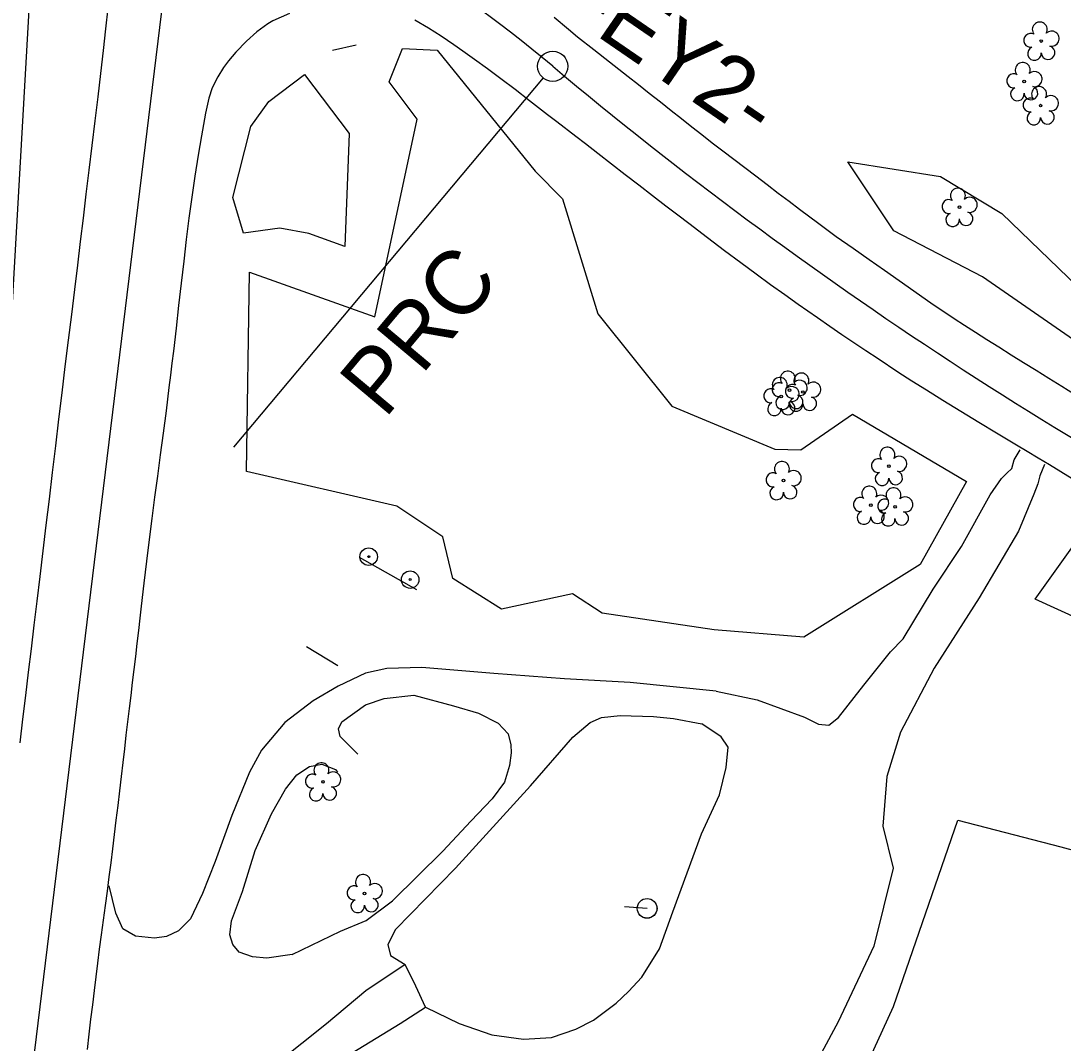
# Model space of a CAD drawing. Extents: x 479429 to 482809, y 488118 to 492379.
# Drawn here: x 481361.5 to 481621, y 490888.5 to 491143.2 of the extents above; entities that cross this region are included whole.
import ezdxf

# ---------------------------------------------------------------- set-up
doc = ezdxf.new("R2010")
doc.units = 0
for name, color, linetype in [('Exist Horizontal Alignment', 7, 'Continuous'), ('Exist Horizontal Alignment Direction Label', 7, 'Continuous'), ('Exist Other Culture Sign', 7, 'Continuous'), ('Exist Other Culture Sign Post CELL', 7, 'Continuous'), ('Exist Roads EOP', 7, 'Continuous'), ('Exist Roads EOP Other', 7, 'Continuous'), ('Exist Roads Soil', 7, 'Continuous'), ('Exist Utilities Other Pole CELL', 7, 'Continuous'), ('Exist Utilities Power Pole CELL', 7, 'Continuous'), ('Exist Vegetation Hedge Row', 7, 'Continuous'), ('Exist Vegetation Tree CELL', 7, 'Continuous'), ('Exist Vegetation Woods Line', 7, 'Continuous')]:
    doc.layers.add(name, color=color, linetype=linetype)

msp = doc.modelspace()

# ---------------------------------------------------------------- linework, layer by layer
at = {"layer": 'Exist Horizontal Alignment'}
for p, q in [((481201.31, 489545.89), (481397.95, 491156.7)), ((481491.52, 491128.98), (481414.4, 491037.01))]:
    msp.add_line(p, q, dxfattribs=at)
msp.add_circle((481493.93, 491131.85), 3.75, dxfattribs=at)
for centre, radius, start, end in [((481278.32, 490874.73), 335.56, 50.0189, 68.4821), ((482162.41, 491929.04), 1040.37, 230.0189, 243.60668)]:
    msp.add_arc(centre, radius, start, end, dxfattribs=at)
at = {"layer": 'Exist Other Culture Sign'}
for p, q in [((481439.13, 491135.83), (481445.01, 491137.18)), ((481460.13, 491001.4), (481445.85, 491009.5)), ((481440.44, 490982.53), (481432.65, 490987.22))]:
    msp.add_line(p, q, dxfattribs=at)
at = {"layer": 'Exist Other Culture Sign Post CELL'}
for centre, radius in [((481448.11, 491009.7), 2.18), ((481448.11, 491009.7), 0.24), ((481458.42, 491003.99), 2.18), ((481458.42, 491003.99), 0.24)]:
    msp.add_circle(centre, radius, dxfattribs=at)
at = {"layer": 'Exist Roads EOP'}
for points in [[(481361.31, 490963.33), (481362.02, 490969.22), (481362.73, 490975.09), (481363.43, 490980.93), (481364.12, 490986.74), (481364.83, 490992.61), (481365.55, 490998.63), (481366.29, 491004.8), (481367.04, 491011.13), (481367.82, 491017.56), (481368.59, 491024.06), (481369.38, 491030.63), (481370.17, 491037.27), (481370.97, 491043.93), (481371.77, 491050.54), (481372.56, 491057.1), (481373.36, 491063.63), (481374.15, 491070.04), (481374.91, 491076.27), (481375.64, 491082.32), (481376.35, 491088.19), (481377.05, 491094.02), (481377.78, 491099.96), (481378.52, 491106), (481379.28, 491112.15), (481380.03, 491118.28), (481380.74, 491124.26), (481381.41, 491130.09), (481382.04, 491135.77), (481382.63, 491141.21), (481383.2, 491146.33)], [(481428.35, 491144.98), (481424.27, 491143.16), (481423.02, 491142.43), (481420.27, 491140.44), (481417.7, 491138.15), (481415.01, 491135.35), (481413.18, 491133.22), (481411.91, 491131.51), (481410.51, 491129.23), (481409.1, 491126.45), (481408.27, 491123.94), (481407.47, 491120.21), (481406.44, 491114.57), (481405.63, 491109.71), (481404.8, 491104.46), (481404.04, 491099.23), (481403.34, 491094), (481402.69, 491088.72), (481402.06, 491083.34), (481401.41, 491077.84), (481400.76, 491072.26), (481400.12, 491066.65), (481399.46, 491060.91), (481399.1, 491057.94), (481398.74, 491054.91), (481398.37, 491051.88), (481397.63, 491046.05), (481396.91, 491040.48), (481396.19, 491035.07), (481395.48, 491029.78), (481394.77, 491024.51), (481394.08, 491019.24), (481393.4, 491013.95), (481392.74, 491008.62), (481392.1, 491003.11), (481391.46, 490997.38), (481391.12, 490994.38), (481390.76, 490991.28), (481390.39, 490988.08), (481390.01, 490984.83), (481389.63, 490981.59), (481389.24, 490978.36), (481388.85, 490975.12), (481388.45, 490971.87), (481388.06, 490968.58), (481387.66, 490965.25), (481387.26, 490961.87), (481386.86, 490958.44), (481386.45, 490954.94), (481386.03, 490951.37), (481385.6, 490947.73), (481385.17, 490944.08), (481384.74, 490940.49), (481384.31, 490936.95), (481383.87, 490933.46), (481383.43, 490929.97), (481382.97, 490926.42), (481382.49, 490922.81), (481381.98, 490919.14), (481381.48, 490915.48), (481381.01, 490911.91), (481380.56, 490908.42), (481380.13, 490905.02), (481379.72, 490901.61), (481379.3, 490898.1), (481378.87, 490894.48), (481378.43, 490890.76), (481377.99, 490886.98)], [(481623.27, 491029.13), (481620.44, 491030.85), (481617.63, 491032.54), (481614.85, 491034.22), (481612.09, 491035.87), (481609.41, 491037.47), (481604.47, 491040.43), (481600, 491043.11), (481595.53, 491045.83), (481591.05, 491048.62), (481586.98, 491051.16), (481583.35, 491053.46), (481579.88, 491055.7), (481574.95, 491058.97), (481571.88, 491061), (481568.91, 491062.98), (481565.93, 491065), (481562.91, 491067.07), (481559.84, 491069.2), (481555.04, 491072.55), (481551.69, 491074.93), (481548.2, 491077.45), (481544.56, 491080.1), (481540.75, 491082.92), (481536.74, 491085.92), (481532.46, 491089.14), (481527.79, 491092.67), (481525.08, 491094.74), (481522.07, 491097.04), (481518.78, 491099.57), (481515.35, 491102.21), (481511.93, 491104.85), (481508.53, 491107.5), (481505.14, 491110.14), (481502.08, 491112.53), (481499.68, 491114.4), (481494.99, 491118), (481492.64, 491119.78), (481488.14, 491123.25), (481484.56, 491126.03), (481481.05, 491128.72), (481477.68, 491131.25), (481474.49, 491133.57), (481471.56, 491135.64), (481469.28, 491137.23), (481466.11, 491139.36), (481462.97, 491141.34), (481459.58, 491143.34)], [(481494.33, 491144.1), (481497.9, 491141.06), (481500.13, 491139.23), (481504.17, 491136), (481508.03, 491132.96), (481512.69, 491129.31), (481515.26, 491127.29), (481517.98, 491125.15), (481520.75, 491122.97), (481523.43, 491120.86), (481526.03, 491118.81), (481528.54, 491116.81), (481531.05, 491114.83), (481533.63, 491112.82), (481536.29, 491110.78), (481539.01, 491108.72), (481541.76, 491106.63), (481544.53, 491104.53), (481547.3, 491102.42), (481550.08, 491100.29), (481552.8, 491098.22), (481555.39, 491096.27), (481560.16, 491092.7), (481564.55, 491089.49), (481568.74, 491086.51), (481572.72, 491083.72), (481576.53, 491081.06), (481580.21, 491078.47), (481583.83, 491075.9), (481588.66, 491072.53), (481591.32, 491070.75), (481593.91, 491069.05), (481596.48, 491067.37), (481599.18, 491065.63), (481602.02, 491063.82), (481604.99, 491061.94), (481608.09, 491060), (481611.2, 491058.07), (481614.33, 491056.14), (481617.5, 491054.17), (481620.7, 491052.17), (481623.9, 491050.22)]]:
    msp.add_lwpolyline(points, dxfattribs=at)
at = {"layer": 'Exist Roads EOP Other'}
msp.add_lwpolyline([(481428.17, 490867), (481422.39, 490868.48), (481421.81, 490869.52), (481431.04, 490878.12), (481442.49, 490885.17), (481455.91, 490893.41), (481462.21, 490897.5), (481459.85, 490902.7), (481457.19, 490908.12), (481447.38, 490901.56), (481437.58, 490893.37), (481425.32, 490883.52), (481418.09, 490877.74), (481408.23, 490868.39), (481399.92, 490859.09), (481388.97, 490845.94), (481382.45, 490838.81), (481380.03, 490835.73), (481377.84, 490834.45), (481375.81, 490834.5), (481372.35, 490839.43)], dxfattribs=at)
at = {"layer": 'Exist Roads Soil'}
for points in [[(481534.63, 490976.16), (481544.85, 490974.08), (481556.6, 490969.73), (481560.08, 490967.97), (481562.72, 490967.76), (481565.08, 490969.61), (481571.42, 490977.73), (481578.08, 490985.98), (481581.2, 490989.26), (481588.66, 491001.58), (481595.69, 491012.24), (481602.84, 491025.14), (481605.72, 491029.16), (481607, 491030.5), (481608.24, 491031.69), (481608.8, 491033.79), (481610.36, 491036.35)], [(481616.42, 491032.67), (481615.19, 491029.81), (481614.71, 491027.83), (481613.7, 491025.31), (481609.88, 491016.02), (481600.16, 490999.48), (481588.93, 490981.94), (481580.52, 490965.98), (481577.16, 490954.97), (481576.12, 490942.54), (481578.73, 490932.1), (481573.86, 490912.69), (481564.98, 490893.85), (481553.68, 490872.8), (481536.24, 490880.65), (481532.06, 490883.51)], [(481534.63, 490976.16), (481513.23, 490978.4), (481496.85, 490979.28), (481479.24, 490980.63), (481461.32, 490982.08), (481452.65, 490981.81), (481447.34, 490980.72), (481440.54, 490977.43), (481434.28, 490973.82), (481427.26, 490968.36), (481421.45, 490961.5), (481418.43, 490956.04), (481414.02, 490945.21), (481409.86, 490933.75), (481406.72, 490925.79), (481403.72, 490919.46), (481400.75, 490916.46), (481397.76, 490915.12), (481394.8, 490914.68), (481390.01, 490915.21), (481386.89, 490916.96), (481385.12, 490920.86), (481383.49, 490927.71)], [(481445.37, 490960.54), (481440.98, 490964.93), (481440.57, 490966.79), (481441.42, 490968.54), (481447.34, 490972.77), (481451.93, 490974.39), (481459.37, 490975.22), (481469.19, 490972.57), (481475.46, 490970.69), (481480.35, 490968.25), (481482.85, 490965.59), (481483.49, 490962.87), (481483.61, 490960.87), (481483.14, 490957.71), (481481.94, 490953.52), (481478.89, 490949.35), (481473.5, 490943.79), (481466.58, 490936.38)], [(481469.68, 490932.1), (481488.36, 490952.66), (481498.94, 490964.78), (481503.23, 490968.39), (481506.11, 490969.68), (481510.73, 490970.17), (481519.02, 490969.88), (481524, 490969.37), (481531.07, 490968.09)], [(481520.51, 490911.99), (481523.81, 490921.2), (481530.94, 490940.67), (481535.45, 490950.39), (481537.13, 490957.21), (481537.64, 490962.25), (481535.86, 490964.86), (481531.07, 490968.09)], [(481429.04, 490910.63), (481422.78, 490909.67), (481419.14, 490910), (481415.86, 490911.21), (481414.24, 490913.08), (481413.54, 490915.5), (481413.91, 490918.96), (481416.7, 490926.33), (481419.87, 490936.49), (481423.93, 490945.64), (481427.4, 490951.77), (481430.25, 490955.4), (481433.35, 490957.47), (481436.45, 490958.02), (481439.86, 490956.66), (481440.37, 490956.06)], [(481429.04, 490910.63), (481441.09, 490916.44), (481447.5, 490919.11), (481454.03, 490923.98), (481466.58, 490936.38)], [(481469.68, 490932.1), (481454.79, 490916.82), (481452.85, 490913.09), (481453.56, 490910.38), (481457.19, 490908.12)], [(481462.21, 490897.5), (481470.62, 490893.39), (481478.74, 490890.62), (481486.69, 490889.49), (481493.6, 490889.92), (481499.68, 490892.03), (481504.07, 490894.25), (481509.74, 490898.46), (481512.8, 490901.42), (481516.12, 490904.99), (481520.51, 490911.99)]]:
    msp.add_lwpolyline(points, dxfattribs=at)
at = {"layer": 'Exist Utilities Other Pole CELL'}
msp.add_circle((481517.44, 490922.1), 2.46, dxfattribs=at)
at = {"layer": 'Exist Utilities Power Pole CELL'}
for q in [(481511.82, 490922.45), (481517.44, 490922.1)]:
    msp.add_line((481517.44, 490922.1), q, dxfattribs=at)
msp.add_circle((481517.44, 490922.1), 2.45, dxfattribs=at)
at = {"layer": 'Exist Vegetation Hedge Row'}
for points in [[(481460.18, 491118.72), (481453.18, 491127.94), (481456.53, 491136.32), (481465.18, 491135.85), (481489.55, 491105.76)], [(481432.13, 491129.77), (481443.21, 491115.13), (481442.18, 491086.93), (481433.17, 491090.24), (481425.94, 491091.5), (481416.95, 491090.28), (481414.3, 491099.19), (481418.78, 491116.86), (481423.2, 491123.07), (481432.13, 491129.77)], [(481693.11, 491019.92), (481682.98, 491025.16), (481647.39, 491047.24), (481600.97, 491079.44), (481578.86, 491090.84), (481567.39, 491108.08), (481590.5, 491104.37), (481605.8, 491095.22), (481626.99, 491074.71), (481637.12, 491068.6), (481645.58, 491053.82), (481657.43, 491046.86), (481662.76, 491049.54), (481676.03, 491063.65), (481693.6, 491069.41), (481698.18, 491061.41)], [(481489.55, 491105.76), (481496.36, 491098.82), (481505.13, 491070.22), (481523.61, 491047.17), (481549.25, 491036.45), (481555.7, 491036.34), (481568.56, 491045.18)], [(481568.56, 491045.18), (481596.93, 491028.41), (481585.46, 491007.73), (481556.43, 490989.64), (481534.15, 490991.48), (481506.24, 490995.63), (481498.82, 491000.45), (481481.15, 490996.59), (481469.03, 491004.26), (481466.53, 491014.61), (481455.13, 491022.31), (481417.67, 491030.93), (481418.45, 491080.58), (481449.6, 491069.46)]]:
    msp.add_lwpolyline(points, dxfattribs=at)
at = {"layer": 'Exist Vegetation Tree CELL'}
for p, q in [((481615.59, 491138.14), (481615.59, 491138.14)), ((481611.35, 491128.07), (481611.35, 491128.07)), ((481615.43, 491122.06), (481615.43, 491122.06)), ((481595.21, 491096.77), (481595.21, 491096.77)), ((481550.84, 491049.62), (481550.84, 491049.62)), ((481552.87, 491051.17), (481552.87, 491051.17)), ((481556.23, 491050.72), (481556.23, 491050.72)), ((481577.65, 491032.23), (481577.65, 491032.23)), ((481551.39, 491028.68), (481551.39, 491028.68)), ((481573.14, 491022.55), (481573.14, 491022.55)), ((481579.17, 491022.13), (481579.17, 491022.13)), ((481436.72, 490953.63), (481436.72, 490953.63)), ((481447.08, 490925.81), (481447.08, 490925.81))]:
    msp.add_line(p, q, dxfattribs=at)
for centre in [(481615.59, 491138.14), (481611.35, 491128.07), (481615.43, 491122.06), (481595.21, 491096.77), (481552.87, 491051.17), (481550.84, 491049.62), (481556.23, 491050.72), (481577.65, 491032.23), (481551.39, 491028.68), (481573.14, 491022.55), (481579.17, 491022.13), (481436.72, 490953.63), (481447.08, 490925.81)]:
    msp.add_circle(centre, 0.326, dxfattribs=at)
for centre, radius, start, end in [((481615.21, 491141.01), 1.86, 330.1651, 219.7134), ((481612.99, 491138.3), 1.73, 62.6636, 279.3457), ((481618.14, 491138.73), 1.9, 257.1011, 134.1999), ((481613.89, 491135.02), 1.69, 111.5671, 6.231), ((481617.27, 491135.24), 1.7, 181.2822, 74.56), ((481610.96, 491130.95), 1.86, 330.1651, 219.7134), ((481608.74, 491128.23), 1.73, 62.6636, 279.3457), ((481613.9, 491128.66), 1.9, 257.1011, 134.1999), ((481613.02, 491125.17), 1.7, 181.2822, 74.56), ((481615.04, 491124.93), 1.86, 330.1651, 219.7134), ((481609.64, 491124.95), 1.69, 111.5671, 6.231), ((481617.98, 491122.65), 1.9, 257.1011, 134.1999), ((481612.82, 491122.21), 1.73, 62.6636, 279.3457), ((481613.72, 491118.94), 1.69, 111.5671, 6.231), ((481617.1, 491119.16), 1.7, 181.2822, 74.56), ((481594.83, 491099.64), 1.86, 330.1651, 219.7134), ((481592.61, 491096.92), 1.73, 62.6636, 279.3457), ((481597.76, 491097.35), 1.9, 257.1011, 134.1999), ((481596.88, 491093.87), 1.7, 181.2822, 74.56), ((481593.51, 491093.64), 1.69, 111.5671, 6.231), ((481550.46, 491052.49), 1.86, 330.1651, 219.7134), ((481552.48, 491054.04), 1.86, 330.1651, 219.7134), ((481555.85, 491053.59), 1.86, 330.1651, 219.7134), ((481548.24, 491049.77), 1.73, 62.6636, 279.3457), ((481550.26, 491051.32), 1.73, 62.6636, 279.3457), ((481553.63, 491050.87), 1.73, 62.6636, 279.3457), ((481553.39, 491050.21), 1.9, 257.1011, 134.1999), ((481555.41, 491051.75), 1.9, 257.1011, 134.1999), ((481558.78, 491051.31), 1.9, 257.1011, 134.1999), ((481551.16, 491048.04), 1.69, 111.5671, 6.231), ((481554.54, 491048.27), 1.7, 181.2822, 74.56), ((481554.53, 491047.6), 1.69, 111.5671, 6.231), ((481557.91, 491047.82), 1.7, 181.2822, 74.56), ((481549.14, 491046.5), 1.69, 111.5671, 6.231), ((481552.52, 491046.72), 1.7, 181.2822, 74.56), ((481577.26, 491035.11), 1.86, 330.1651, 219.7134), ((481551.01, 491031.56), 1.86, 330.1651, 219.7134), ((481575.04, 491032.39), 1.73, 62.6636, 279.3457), ((481580.2, 491032.82), 1.9, 257.1011, 134.1999), ((481548.78, 491028.84), 1.73, 62.6636, 279.3457), ((481553.94, 491029.27), 1.9, 257.1011, 134.1999), ((481575.94, 491029.11), 1.69, 111.5671, 6.231), ((481579.32, 491029.33), 1.7, 181.2822, 74.56), ((481549.69, 491025.56), 1.69, 111.5671, 6.231), ((481553.06, 491025.78), 1.7, 181.2822, 74.56), ((481572.76, 491025.42), 1.86, 330.1651, 219.7134), ((481578.79, 491025.01), 1.86, 330.1651, 219.7134), ((481570.54, 491022.7), 1.73, 62.6636, 279.3457), ((481575.69, 491023.14), 1.9, 257.1011, 134.1999), ((481576.57, 491022.29), 1.73, 62.6636, 279.3457), ((481581.72, 491022.72), 1.9, 257.1011, 134.1999), ((481571.44, 491019.43), 1.69, 111.5671, 6.231), ((481574.81, 491019.65), 1.7, 181.2822, 74.56), ((481577.47, 491019.01), 1.69, 111.5671, 6.231), ((481580.85, 491019.23), 1.7, 181.2822, 74.56), ((481436.33, 490956.5), 1.86, 330.1651, 219.7134), ((481434.11, 490953.78), 1.73, 62.6636, 279.3457), ((481439.27, 490954.22), 1.9, 257.1011, 134.1999), ((481435.01, 490950.51), 1.69, 111.5671, 6.231), ((481438.39, 490950.73), 1.7, 181.2822, 74.56), ((481446.7, 490928.68), 1.86, 330.1651, 219.7134), ((481444.48, 490925.96), 1.73, 62.6636, 279.3457), ((481449.63, 490926.39), 1.9, 257.1011, 134.1999), ((481445.38, 490922.69), 1.69, 111.5671, 6.231), ((481448.76, 490922.91), 1.7, 181.2822, 74.56)]:
    msp.add_arc(centre, radius, start, end, dxfattribs=at)
at = {"layer": 'Exist Vegetation Woods Line'}
for points in [[(481345.68, 491317.77), (481353.11, 491285.94), (481369.31, 491248.07), (481358.47, 491058.43), (481341.15, 491052.66), (481321.21, 491054.95), (481298.3, 491063.81), (481271.21, 491099.5), (481228.18, 491111.26), (481224.55, 491104.53), (481200.99, 491109.54), (481185.6, 491126.62), (481153.65, 491129.73), (481134.53, 491138.7), (481129.51, 491142.77)], [(481449.6, 491069.46), (481460.18, 491118.72)], [(481686.54, 490966.1), (481614.09, 490999.09), (481623.59, 491012.51), (481687.46, 490973.62)], [(481545.33, 490841.63), (481544.99, 490846.9), (481553.47, 490860.44), (481564.99, 490867.53), (481578.8, 490897.64), (481594.78, 490944.1), (481620.43, 490937.44), (481682.93, 490920.46), (481631.17, 490831.15)]]:
    msp.add_lwpolyline(points, dxfattribs=at)

# ---------------------------------------------------------------- texts
at = {"layer": 'Exist Horizontal Alignment'}
msp.add_text('PRC', height=16, rotation=50.0189, dxfattribs=at).set_placement((481452.1, 491043.82))
at = {"layer": 'Exist Horizontal Alignment Direction Label'}
msp.add_text('-EY2-', height=16, rotation=325.5285, dxfattribs=at).set_placement((481498.45, 491143.83))

doc.saveas('drawing.dxf')
